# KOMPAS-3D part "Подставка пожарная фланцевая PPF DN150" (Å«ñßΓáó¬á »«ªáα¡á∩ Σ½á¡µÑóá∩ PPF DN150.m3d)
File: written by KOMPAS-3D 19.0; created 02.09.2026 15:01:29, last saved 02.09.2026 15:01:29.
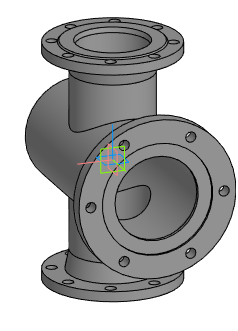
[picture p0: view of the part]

Document properties: Автор: Энергия; Полное имя файла: Z:\3.Личные\sachek\Dendor\_3D для проектировщиков\11.5 Подставка пожарная фланцевая PPF\stp\Подставка пожарная фланцевая PPF DN150.m3d

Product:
- Part/product: Подставка пожарная фланцевая PPF DN150

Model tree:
1. Операция без истории:1  (labels: Подставка пожарная фланцевая PPF DN150)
